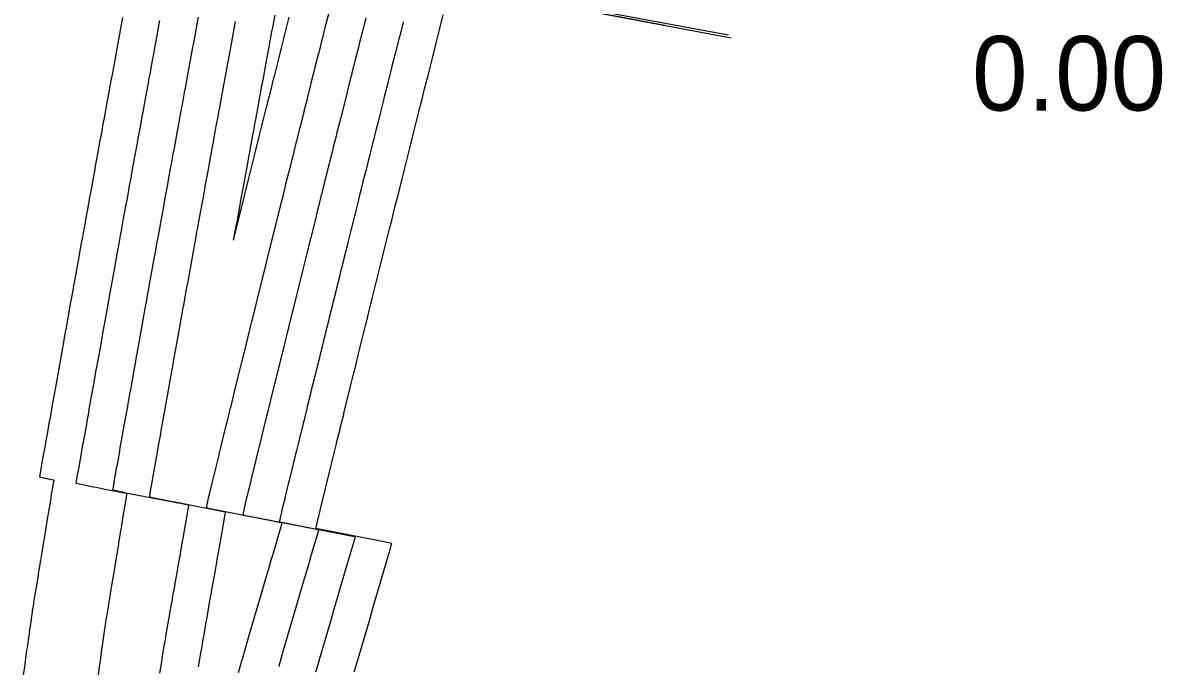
# Model space of a CAD drawing. Extents: x 688474 to 694748, y 765018 to 767373.
# Drawn here: x 688679.3 to 688771, y 766120.4 to 766172.2 of the extents above; entities that cross this region are included whole.
import ezdxf

# ---------------------------------------------------------------- set-up
doc = ezdxf.new("R2010")
doc.units = 0
for name, color, linetype in [('Prop_Contours_Major', 7, 'Continuous'), ('Prop_Contours_Minor', 7, 'Continuous'), ('R_Horz Alg Annot', 7, 'Continuous')]:
    doc.layers.add(name, color=color, linetype=linetype)

msp = doc.modelspace()

# ---------------------------------------------------------------- linework, layer by layer
at = {"layer": 'Prop_Contours_Major'}
for points in [[(688702.004, 766177.465), (688736.349, 766171.002)], [(688736.132, 766171.209), (688702.257, 766177.488)], [(688699.603, 766172.821), (688699.417, 766171.817), (688699.38, 766171.614), (688699.196, 766170.62), (688699.156, 766170.407), (688698.974, 766169.423), (688698.947, 766169.274), (688698.919, 766169.125), (688698.723, 766168.06), (688698.692, 766167.895), (688698.526, 766166.991), (688698.491, 766166.803), (688698.306, 766165.797), (688698.268, 766165.593), (688698.083, 766164.583), (688698.048, 766164.394), (688698.036, 766164.33), (688697.86, 766163.369), (688697.828, 766163.194), (688697.817, 766163.136), (688697.637, 766162.153), (688697.608, 766161.996), (688697.598, 766161.943), (688697.414, 766160.936), (688697.38, 766160.752), (688697.191, 766159.717), (688697.163, 766159.561), (688696.963, 766158.466), (688696.946, 766158.372), (688696.889, 766158.061), (688696.74, 766157.245), (688696.732, 766157.198), (688696.521, 766156.037), (688696.514, 766156), (688696.299, 766154.818), (688696.282, 766154.727), (688696.28, 766154.715), (688696.28, 766154.711), (688696.281, 766154.715), (688696.284, 766154.727), (688696.307, 766154.819), (688696.603, 766156.01), (688696.9, 766157.201), (688697.109, 766158.039), (688697.196, 766158.39), (688697.494, 766159.583), (688697.791, 766160.774), (688698.089, 766161.965), (688698.387, 766163.156), (688698.685, 766164.343), (688698.983, 766165.533), (688699.282, 766166.724), (688699.543, 766167.764), (688699.58, 766167.91), (688699.879, 766169.099), (688700.179, 766170.288), (688700.478, 766171.478), (688700.779, 766172.667)]]:
    msp.add_lwpolyline(points, dxfattribs=at)
at = {"layer": 'Prop_Contours_Minor'}
for points in [[(688731.004, 766171.998), (688704.947, 766176.901)], [(688704.007, 766173.22), (688703.748, 766172.195), (688703.706, 766172.031), (688703.447, 766171.004), (688703.406, 766170.842), (688703.147, 766169.814), (688703.107, 766169.653), (688702.847, 766168.624), (688702.807, 766168.464), (688702.525, 766167.344), (688702.482, 766167.172), (688702.249, 766166.243), (688702.209, 766166.086), (688701.95, 766165.053), (688701.911, 766164.897), (688701.651, 766163.862), (688701.613, 766163.708), (688701.353, 766162.671), (688701.315, 766162.519), (688701.055, 766161.481), (688701.017, 766161.33), (688700.757, 766160.29), (688700.72, 766160.14), (688700.46, 766159.099), (688700.423, 766158.951), (688700.144, 766157.835), (688700.05, 766157.457), (688699.857, 766156.681), (688699.83, 766156.572), (688699.569, 766155.526), (688699.534, 766155.383), (688699.273, 766154.335), (688699.238, 766154.193), (688698.977, 766153.144), (688698.942, 766153.004), (688698.682, 766151.953), (688698.647, 766151.814), (688698.386, 766150.762), (688698.352, 766150.624), (688698.091, 766149.571), (688698.058, 766149.434), (688697.784, 766148.328), (688697.742, 766148.156), (688697.635, 766147.725), (688697.494, 766147.155), (688697.469, 766147.055), (688697.19, 766145.924), (688697.115, 766145.62), (688696.906, 766144.773), (688696.882, 766144.675), (688696.621, 766143.614), (688696.589, 766143.485), (688696.328, 766142.422), (688696.296, 766142.295), (688696.035, 766141.23), (688696.004, 766141.105), (688695.742, 766140.038), (688695.712, 766139.915), (688695.439, 766138.805), (688695.388, 766138.593), (688695.246, 766138.013), (688695.143, 766137.594), (688695.069, 766137.293), (688694.859, 766136.433), (688694.837, 766136.344), (688694.575, 766135.271), (688694.546, 766135.153), (688694.279, 766134.062), (688694.274, 766134.041), (688694.27, 766134.021), (688694.265, 766134), (688694.26, 766133.979), (688694.234, 766133.855), (688694.225, 766133.813), (688694.124, 766133.339), (688694.119, 766133.262), (688694.14, 766133.202), (688694.187, 766133.159), (688694.26, 766133.133), (688699.31, 766132.146), (688700.175, 766131.976), (688700.182, 766131.974), (688700.186, 766131.97), (688700.187, 766131.965), (688700.186, 766131.958), (688700.095, 766131.648), (688699.774, 766130.555), (688699.74, 766130.439), (688699.419, 766129.344), (688699.329, 766129.035), (688699.072, 766128.157), (688699.001, 766127.917), (688698.787, 766127.184), (688698.705, 766126.905), (688698.382, 766125.799), (688698.299, 766125.514), (688698.037, 766124.617), (688697.956, 766124.341), (688697.692, 766123.435), (688697.614, 766123.168), (688697.34, 766122.23), (688697.166, 766121.63), (688697.156, 766121.597), (688697.129, 766121.499), (688697.001, 766121.048), (688696.938, 766120.821), (688696.675, 766119.886)], [(688687.364, 766172.632), (688687.177, 766171.62), (688687.142, 766171.427), (688687.035, 766170.848), (688686.927, 766170.265), (688686.899, 766170.115), (688686.73, 766169.196), (688686.699, 766169.027), (688686.519, 766168.049), (688686.488, 766167.879), (688686.456, 766167.708), (688686.29, 766166.805), (688686.254, 766166.609), (688686.076, 766165.639), (688686.045, 766165.47), (688686.014, 766165.301), (688685.849, 766164.398), (688685.812, 766164.2), (688685.628, 766163.194), (688685.592, 766162.995), (688685.408, 766161.991), (688685.371, 766161.79), (688685.167, 766160.672), (688685.094, 766160.271), (688684.965, 766159.564), (688684.934, 766159.389), (688684.75, 766158.379), (688684.713, 766158.174), (688684.531, 766157.176), (688684.493, 766156.969), (688684.312, 766155.972), (688684.275, 766155.764), (688684.098, 766154.789), (688684.069, 766154.628), (688684.04, 766154.468), (688683.876, 766153.564), (688683.838, 766153.353), (688683.659, 766152.36), (688683.62, 766152.147), (688683.422, 766151.047), (688683.355, 766150.68), (688683.302, 766150.383), (688683.205, 766149.847), (688683.184, 766149.73), (688682.985, 766148.62), (688682.928, 766148.308), (688682.786, 766147.513), (688682.755, 766147.34), (688682.575, 766146.341), (688682.549, 766146.192), (688682.522, 766146.044), (688682.36, 766145.138), (688682.333, 766144.987), (688682.306, 766144.836), (688682.143, 766143.93), (688682.117, 766143.782), (688682.09, 766143.633), (688681.928, 766142.723), (688681.902, 766142.576), (688681.875, 766142.43), (688681.704, 766141.469), (688681.669, 766141.273), (688681.551, 766140.612), (688681.472, 766140.165), (688681.461, 766140.107), (688681.283, 766139.103), (688681.244, 766138.888), (688681.068, 766137.894), (688681.03, 766137.684), (688680.847, 766136.647), (688680.811, 766136.449), (688680.674, 766135.674), (688680.674, 766135.671), (688680.675, 766135.67), (688680.676, 766135.668), (688680.678, 766135.668), (688681.788, 766135.435), (688681.804, 766135.429), (688681.815, 766135.419), (688681.82, 766135.406), (688681.819, 766135.388), (688681.772, 766135.106), (688681.601, 766134.071), (688681.575, 766133.916), (688681.55, 766133.761), (688681.399, 766132.851), (688681.375, 766132.708), (688681.352, 766132.564), (688681.195, 766131.612), (688681.176, 766131.499), (688681.158, 766131.386), (688681.021, 766130.552), (688680.975, 766130.274), (688680.806, 766129.244), (688680.78, 766129.082), (688680.753, 766128.92), (688680.605, 766128.011), (688680.582, 766127.873), (688680.56, 766127.735), (688680.408, 766126.8), (688680.386, 766126.664), (688680.364, 766126.528), (688680.204, 766125.544), (688680.182, 766125.41), (688680.097, 766124.881), (688680.092, 766124.85), (688680.087, 766124.819), (688680.082, 766124.787), (688680.078, 766124.756), (688680.01, 766124.284), (688679.993, 766124.163), (688679.849, 766123.16), (688679.831, 766123.031), (688679.812, 766122.901), (688679.675, 766121.94), (688679.658, 766121.817), (688679.64, 766121.694), (688679.491, 766120.644), (688679.484, 766120.597), (688679.331, 766119.514)], [(688685.388, 766119.546), (688685.533, 766120.568), (688685.553, 766120.708), (688685.573, 766120.849), (688685.705, 766121.775), (688685.726, 766121.922), (688685.747, 766122.069), (688685.889, 766123.063), (688685.91, 766123.208), (688685.972, 766123.639), (688685.977, 766123.675), (688685.982, 766123.71), (688685.988, 766123.745), (688685.994, 766123.781), (688686.079, 766124.306), (688686.098, 766124.426), (688686.257, 766125.405), (688686.281, 766125.555), (688686.306, 766125.706), (688686.453, 766126.612), (688686.478, 766126.764), (688686.503, 766126.916), (688686.651, 766127.825), (688686.675, 766127.973), (688686.699, 766128.121), (688686.871, 766129.167), (688686.919, 766129.46), (688687.053, 766130.274), (688687.072, 766130.39), (688687.091, 766130.507), (688687.245, 766131.443), (688687.271, 766131.599), (688687.297, 766131.755), (688687.447, 766132.664), (688687.471, 766132.807), (688687.494, 766132.951), (688687.668, 766133.996), (688687.715, 766134.282), (688687.716, 766134.298), (688687.711, 766134.311), (688687.701, 766134.32), (688687.686, 766134.325), (688685.945, 766134.659), (688685.713, 766134.704), (688685.48, 766134.75), (688685.248, 766134.797), (688685.016, 766134.845), (688683.667, 766135.126), (688683.649, 766135.132), (688683.637, 766135.143), (688683.632, 766135.158), (688683.632, 766135.176), (688683.772, 766135.965), (688683.829, 766136.285), (688683.948, 766136.956), (688683.991, 766137.2), (688684.034, 766137.443), (688684.2, 766138.376), (688684.216, 766138.463), (688684.42, 766139.611), (688684.5, 766140.058), (688684.516, 766140.148), (688684.635, 766140.816), (688684.685, 766141.1), (688684.845, 766141.994), (688684.9, 766142.304), (688685.021, 766142.982), (688685.065, 766143.227), (688685.109, 766143.472), (688685.276, 766144.405), (688685.291, 766144.489), (688685.492, 766145.61), (688685.547, 766145.916), (688685.709, 766146.822), (688685.752, 766147.059), (688685.882, 766147.785), (688685.932, 766148.061), (688686.144, 766149.239), (688686.173, 766149.401), (688686.253, 766149.844), (688686.284, 766150.016), (688686.368, 766150.484), (688686.576, 766151.637), (688686.63, 766151.935), (688686.754, 766152.622), (688686.799, 766152.869), (688686.844, 766153.116), (688687.012, 766154.047), (688687.027, 766154.128), (688687.231, 766155.252), (688687.245, 766155.332), (688687.449, 766156.457), (688687.503, 766156.749), (688687.628, 766157.44), (688687.673, 766157.688), (688687.718, 766157.936), (688687.888, 766158.867), (688687.902, 766158.946), (688688.047, 766159.741), (688688.115, 766160.113), (688688.327, 766161.276), (688688.38, 766161.564), (688688.507, 766162.258), (688688.552, 766162.507), (688688.598, 766162.756), (688688.768, 766163.685), (688688.82, 766163.971), (688688.948, 766164.667), (688688.993, 766164.916), (688689.039, 766165.165), (688689.21, 766166.094), (688689.262, 766166.379), (688689.39, 766167.075), (688689.436, 766167.324), (688689.482, 766167.574), (688689.653, 766168.506), (688689.699, 766168.752), (688689.851, 766169.577), (688689.881, 766169.74), (688690.097, 766170.912), (688690.149, 766171.193), (688690.32, 766172.116), (688690.372, 766172.396)], [(688690.359, 766119.865), (688690.54, 766120.956), (688690.559, 766121.073), (688690.744, 766122.195), (688690.759, 766122.28), (688690.84, 766122.77), (688690.844, 766122.796), (688690.849, 766122.822), (688690.955, 766123.43), (688690.96, 766123.459), (688691.162, 766124.61), (688691.176, 766124.69), (688691.373, 766125.817), (688691.387, 766125.895), (688691.585, 766127.023), (688691.599, 766127.1), (688691.797, 766128.23), (688691.847, 766128.511), (688692.011, 766129.442), (688692.021, 766129.5), (688692.223, 766130.643), (688692.235, 766130.715), (688692.436, 766131.85), (688692.448, 766131.92), (688692.649, 766133.056), (688692.705, 766133.369), (688692.705, 766133.374), (688692.703, 766133.378), (688692.7, 766133.381), (688692.695, 766133.383), (688692.025, 766133.514), (688691.911, 766133.536), (688691.797, 766133.558), (688691.684, 766133.58), (688691.57, 766133.602), (688688.057, 766134.276), (688687.909, 766134.305), (688687.76, 766134.334), (688687.611, 766134.364), (688687.463, 766134.395), (688686.677, 766134.559), (688686.633, 766134.575), (688686.604, 766134.601), (688686.59, 766134.637), (688686.592, 766134.684), (688686.716, 766135.384), (688686.745, 766135.55), (688686.912, 766136.489), (688686.94, 766136.645), (688686.967, 766136.801), (688687.128, 766137.705), (688687.154, 766137.851), (688687.18, 766137.996), (688687.363, 766139.03), (688687.448, 766139.503), (688687.575, 766140.216), (688687.599, 766140.353), (688687.772, 766141.324), (688687.811, 766141.539), (688687.985, 766142.515), (688688.014, 766142.673), (688688.042, 766142.83), (688688.204, 766143.735), (688688.242, 766143.95), (688688.42, 766144.941), (688688.458, 766145.155), (688688.642, 766146.177), (688688.672, 766146.345), (688688.831, 766147.231), (688688.884, 766147.525), (688689.081, 766148.623), (688689.109, 766148.776), (688689.212, 766149.347), (688689.306, 766149.872), (688689.324, 766149.97), (688689.504, 766150.968), (688689.542, 766151.18), (688689.719, 766152.155), (688689.747, 766152.314), (688689.776, 766152.474), (688689.94, 766153.378), (688689.978, 766153.59), (688690.158, 766154.583), (688690.197, 766154.795), (688690.377, 766155.789), (688690.415, 766155.999), (688690.592, 766156.973), (688690.622, 766157.134), (688690.651, 766157.294), (688690.82, 766158.225), (688690.851, 766158.395), (688690.995, 766159.187), (688691.064, 766159.564), (688691.255, 766160.608), (688691.293, 766160.818), (688691.471, 766161.791), (688691.501, 766161.952), (688691.53, 766162.114), (688691.695, 766163.018), (688691.734, 766163.227), (688691.912, 766164.2), (688691.942, 766164.361), (688691.971, 766164.523), (688692.137, 766165.427), (688692.176, 766165.635), (688692.354, 766166.608), (688692.384, 766166.77), (688692.414, 766166.932), (688692.584, 766167.853), (688692.617, 766168.035), (688692.801, 766169.033), (688692.831, 766169.196), (688693.025, 766170.244), (688693.063, 766170.452), (688693.247, 766171.448), (688693.285, 766171.656), (688693.47, 766172.653)], [(688693.483, 766120.375), (688693.512, 766120.546), (688693.694, 766121.648), (688693.732, 766121.879), (688693.785, 766122.194), (688693.788, 766122.218), (688693.792, 766122.241), (688693.796, 766122.265), (688693.801, 766122.289), (688693.895, 766122.83), (688693.919, 766122.967), (688694.098, 766123.988), (688694.131, 766124.176), (688694.309, 766125.192), (688694.343, 766125.385), (688694.52, 766126.395), (688694.555, 766126.594), (688694.75, 766127.701), (688694.801, 766127.988), (688694.944, 766128.803), (688694.981, 766129.011), (688695.156, 766130.006), (688695.185, 766130.166), (688695.369, 766131.21), (688695.398, 766131.373), (688695.484, 766131.863), (688695.604, 766132.538), (688695.646, 766132.779), (688695.647, 766132.8), (688695.641, 766132.817), (688695.628, 766132.828), (688695.607, 766132.835), (688692.242, 766133.494), (688692.022, 766133.537), (688691.801, 766133.579), (688691.581, 766133.622), (688691.361, 766133.664), (688690.169, 766133.893), (688690.104, 766133.906), (688690.04, 766133.918), (688689.975, 766133.931), (688689.91, 766133.945), (688689.651, 766133.999), (688689.596, 766134.019), (688689.56, 766134.052), (688689.543, 766134.097), (688689.545, 766134.156), (688689.67, 766134.861), (688689.683, 766134.933), (688689.876, 766136.022), (688689.9, 766136.159), (688690.09, 766137.227), (688690.114, 766137.365), (688690.309, 766138.459), (688690.332, 766138.588), (688690.401, 766138.975), (688690.505, 766139.561), (688690.544, 766139.781), (688690.557, 766139.854), (688690.734, 766140.843), (688690.759, 766140.983), (688690.949, 766142.048), (688690.974, 766142.189), (688691.165, 766143.253), (688691.19, 766143.394), (688691.352, 766144.299), (688691.394, 766144.529), (688691.435, 766144.76), (688691.603, 766145.699), (688691.623, 766145.805), (688691.782, 766146.692), (688691.835, 766146.99), (688692.021, 766148.021), (688692.054, 766148.207), (688692.163, 766148.809), (688692.251, 766149.297), (688692.28, 766149.456), (688692.465, 766150.483), (688692.491, 766150.627), (688692.683, 766151.688), (688692.709, 766151.832), (688692.901, 766152.892), (688692.927, 766153.038), (688693.119, 766154.097), (688693.145, 766154.243), (688693.31, 766155.147), (688693.351, 766155.375), (688693.392, 766155.603), (688693.557, 766156.506), (688693.583, 766156.653), (688693.785, 766157.758), (688693.836, 766158.043), (688693.948, 766158.654), (688694.009, 766158.989), (688694.021, 766159.056), (688694.215, 766160.12), (688694.242, 766160.267), (688694.435, 766161.324), (688694.462, 766161.472), (688694.628, 766162.376), (688694.669, 766162.602), (688694.711, 766162.829), (688694.876, 766163.733), (688694.904, 766163.881), (688695.07, 766164.785), (688695.111, 766165.011), (688695.153, 766165.238), (688695.319, 766166.141), (688695.346, 766166.29), (688695.518, 766167.223), (688695.554, 766167.42), (688695.591, 766167.617), (688695.749, 766168.478), (688695.782, 766168.653), (688695.957, 766169.602), (688695.998, 766169.828), (688696.04, 766170.054), (688696.207, 766170.957), (688696.235, 766171.107), (688696.43, 766172.161), (688696.458, 766172.312)], [(688706.939, 766172.602), (688706.712, 766171.705), (688706.675, 766171.558), (688706.638, 766171.412), (688706.412, 766170.516), (688706.375, 766170.369), (688706.338, 766170.222), (688706.112, 766169.327), (688706.075, 766169.179), (688706.038, 766169.032), (688705.813, 766168.138), (688705.776, 766167.99), (688705.738, 766167.841), (688705.474, 766166.79), (688705.433, 766166.627), (688705.21, 766165.74), (688705.161, 766165.545), (688704.916, 766164.568), (688704.879, 766164.42), (688704.842, 766164.273), (688704.617, 766163.377), (688704.58, 766163.231), (688704.544, 766163.084), (688704.319, 766162.187), (688704.282, 766162.041), (688704.246, 766161.895), (688704.021, 766160.996), (688703.984, 766160.851), (688703.948, 766160.705), (688703.723, 766159.806), (688703.687, 766159.661), (688703.651, 766159.516), (688703.426, 766158.615), (688703.39, 766158.471), (688703.354, 766158.326), (688703.098, 766157.302), (688702.999, 766156.906), (688702.823, 766156.199), (688702.769, 766155.982), (688702.535, 766155.043), (688702.5, 766154.9), (688702.464, 766154.757), (688702.239, 766153.852), (688702.186, 766153.639), (688701.943, 766152.661), (688701.891, 766152.449), (688701.648, 766151.47), (688701.595, 766151.259), (688701.353, 766150.279), (688701.3, 766150.068), (688701.058, 766149.088), (688701.006, 766148.878), (688700.736, 766147.79), (688700.649, 766147.435), (688700.574, 766147.134), (688700.445, 766146.61), (688700.413, 766146.482), (688700.14, 766145.376), (688700.068, 766145.081), (688699.877, 766144.31), (688699.831, 766144.123), (688699.587, 766143.132), (688699.537, 766142.926), (688699.294, 766141.94), (688699.244, 766141.736), (688699.001, 766140.749), (688698.951, 766140.545), (688698.708, 766139.557), (688698.659, 766139.354), (688698.404, 766138.316), (688698.362, 766138.146), (688698.199, 766137.482), (688698.091, 766137.04), (688697.927, 766136.369), (688697.816, 766135.916), (688697.767, 766135.715), (688697.541, 766134.79), (688697.492, 766134.591), (688697.241, 766133.56), (688697.229, 766133.513), (688697.218, 766133.466), (688697.208, 766133.419), (688697.198, 766133.372), (688697.157, 766133.182), (688697.137, 766133.087), (688697.117, 766132.993), (688697.062, 766132.731), (688697.058, 766132.678), (688697.072, 766132.637), (688697.105, 766132.607), (688697.155, 766132.589), (688700.777, 766131.881), (688703.104, 766131.426), (688703.118, 766131.421), (688703.127, 766131.412), (688703.131, 766131.4), (688703.129, 766131.385), (688703.04, 766131.084), (688702.745, 766130.078), (688702.686, 766129.875), (688702.399, 766128.896), (688702.34, 766128.694), (688702.045, 766127.687), (688701.998, 766127.528), (688701.738, 766126.641), (688701.658, 766126.367), (688701.361, 766125.35), (688701.304, 766125.153), (688701.016, 766124.168), (688700.959, 766123.973), (688700.671, 766122.985), (688700.614, 766122.792), (688700.446, 766122.214), (688700.299, 766121.709), (688700.269, 766121.608), (688700.125, 766121.114), (688700.116, 766121.084), (688700.108, 766121.054), (688700.099, 766121.024), (688700.091, 766120.994), (688699.961, 766120.533), (688699.927, 766120.413)], [(688709.944, 766172.271), (688709.904, 766172.116), (688709.643, 766171.082), (688709.604, 766170.926), (688709.343, 766169.893), (688709.304, 766169.736), (688709.044, 766168.704), (688709.004, 766168.546), (688708.744, 766167.515), (688708.704, 766167.356), (688708.425, 766166.246), (688708.383, 766166.081), (688708.143, 766165.126), (688708.108, 766164.986), (688707.847, 766163.947), (688707.807, 766163.785), (688707.549, 766162.757), (688707.508, 766162.595), (688707.251, 766161.568), (688707.21, 766161.405), (688706.953, 766160.378), (688706.912, 766160.215), (688706.656, 766159.188), (688706.615, 766159.024), (688706.359, 766157.999), (688706.318, 766157.834), (688706.049, 766156.758), (688706.025, 766156.663), (688705.947, 766156.349), (688705.752, 766155.565), (688705.73, 766155.477), (688705.469, 766154.429), (688705.427, 766154.262), (688705.173, 766153.239), (688705.131, 766153.072), (688704.878, 766152.049), (688704.836, 766151.881), (688704.582, 766150.859), (688704.54, 766150.69), (688704.287, 766149.669), (688704.245, 766149.499), (688703.992, 766148.479), (688703.95, 766148.308), (688703.698, 766147.289), (688703.656, 766147.117), (688703.536, 766146.632), (688703.388, 766146.036), (688703.371, 766145.966), (688703.094, 766144.845), (688703.02, 766144.543), (688702.803, 766143.665), (688702.778, 766143.563), (688702.523, 766142.528), (688702.48, 766142.353), (688702.23, 766141.337), (688702.187, 766141.162), (688701.938, 766140.147), (688701.894, 766139.97), (688701.645, 766138.956), (688701.602, 766138.779), (688701.353, 766137.766), (688701.31, 766137.588), (688701.148, 766136.927), (688701.036, 766136.469), (688700.77, 766135.384), (688700.726, 766135.204), (688700.479, 766134.194), (688700.435, 766134.013), (688700.188, 766133.003), (688700.177, 766132.957), (688700.167, 766132.912), (688700.156, 766132.866), (688700.147, 766132.82), (688700.055, 766132.385), (688700.041, 766132.32), (688700.027, 766132.255), (688699.999, 766132.124), (688699.997, 766132.094), (688700.005, 766132.071), (688700.023, 766132.055), (688700.051, 766132.045), (688702.331, 766131.599), (688706.032, 766130.875), (688706.055, 766130.867), (688706.069, 766130.854), (688706.075, 766130.835), (688706.071, 766130.811), (688705.994, 766130.549), (688705.678, 766129.469), (688705.63, 766129.307), (688705.332, 766128.289), (688705.284, 766128.125), (688704.986, 766127.109), (688704.938, 766126.944), (688704.687, 766126.086), (688704.611, 766125.828), (688704.296, 766124.748), (688704.247, 766124.58), (688703.951, 766123.568), (688703.902, 766123.399), (688703.606, 766122.388), (688703.557, 766122.217), (688703.262, 766121.207), (688703.212, 766121.034), (688703.069, 766120.545), (688703.063, 766120.522), (688703.056, 766120.499), (688703.05, 766120.476), (688703.043, 766120.453), (688702.898, 766119.939)], [(688706.01, 766119.963), (688706.187, 766120.573), (688706.532, 766121.753), (688706.876, 766122.934), (688707.221, 766124.115), (688707.566, 766125.295), (688707.64, 766125.55), (688707.912, 766126.476), (688708.257, 766127.657), (688708.603, 766128.838), (688708.95, 766130.019), (688709.014, 766130.237), (688709.019, 766130.27), (688709.011, 766130.295), (688708.992, 766130.314), (688708.961, 766130.325), (688703.196, 766131.452), (688702.946, 766131.501), (688702.941, 766131.503), (688702.937, 766131.506), (688702.936, 766131.51), (688702.936, 766131.516), (688702.946, 766131.565), (688703.111, 766132.341), (688703.114, 766132.357), (688703.118, 766132.374), (688703.405, 766133.549), (688703.425, 766133.631), (688703.696, 766134.74), (688703.716, 766134.821), (688703.989, 766135.937), (688704.099, 766136.383), (688704.282, 766137.13), (688704.572, 766138.313), (688704.591, 766138.391), (688704.864, 766139.504), (688704.883, 766139.58), (688705.157, 766140.695), (688705.176, 766140.77), (688705.45, 766141.886), (688705.468, 766141.96), (688705.745, 766143.082), (688705.977, 766144.023), (688706.041, 766144.282), (688706.333, 766145.466), (688706.491, 766146.105), (688706.629, 766146.663), (688706.92, 766147.839), (688706.937, 766147.909), (688707.214, 766149.03), (688707.51, 766150.22), (688707.805, 766151.411), (688708.101, 766152.601), (688708.397, 766153.791), (688708.694, 766154.986), (688708.906, 766155.838), (688708.993, 766156.184), (688709.286, 766157.362), (688709.584, 766158.552), (688709.881, 766159.742), (688710.179, 766160.932), (688710.477, 766162.122), (688710.775, 766163.312), (688711.075, 766164.506), (688711.336, 766165.545), (688711.387, 766165.746), (688711.672, 766166.881), (688711.972, 766168.07), (688712.272, 766169.26), (688712.573, 766170.454), (688712.874, 766171.644), (688713.174, 766172.833)]]:
    msp.add_lwpolyline(points, dxfattribs=at)

# ---------------------------------------------------------------- texts
at = {"layer": 'R_Horz Alg Annot'}
msp.add_text('0.00', height=6, dxfattribs=at).set_placement((688755.729, 766165.143))

doc.saveas('drawing.dxf')
